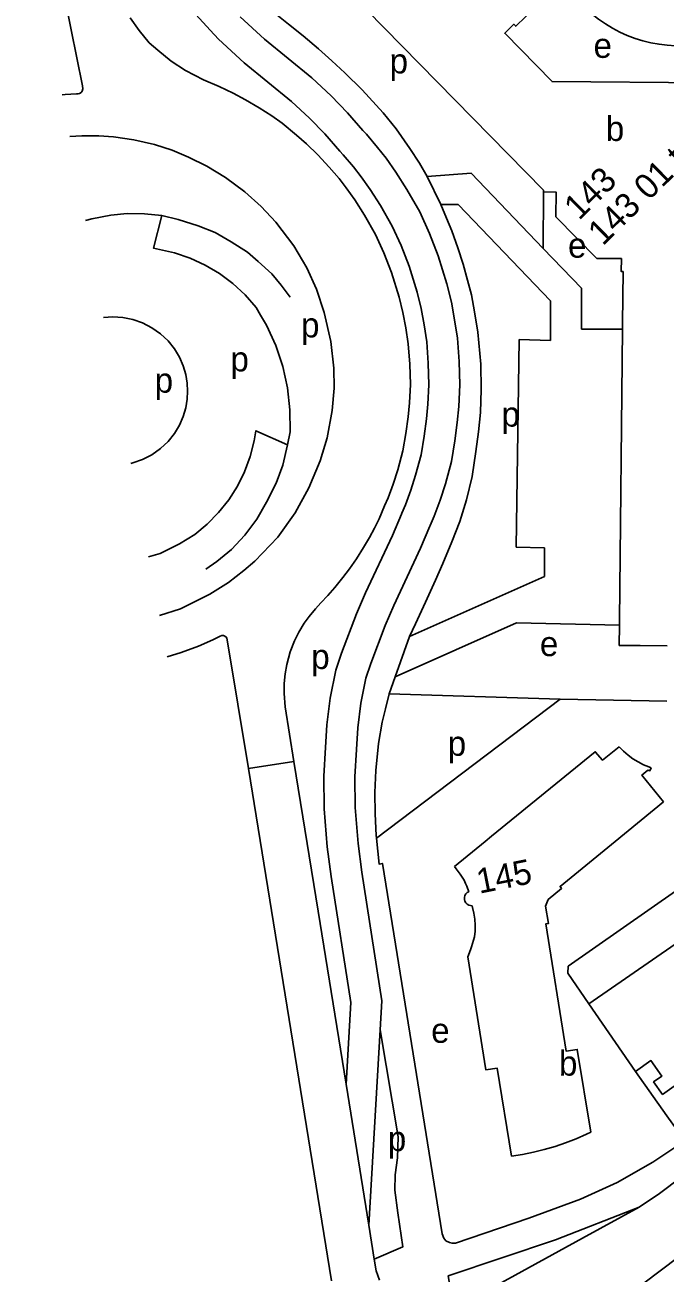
# Model space of a CAD drawing. Extents: x 159261 to 160849, y 382514 to 384534.
# Drawn here: x 159331.2 to 159434.5, y 383430.4 to 383631.8 of the extents above; entities that cross this region are included whole.
import ezdxf

# ---------------------------------------------------------------- set-up
doc = ezdxf.new("R2010")
doc.units = 0
for name, color, linetype in [('BLT_Basislijn', 7, 'Continuous'), ('BLT_Bebouwing', 7, 'Continuous'), ('BLT_Centroide', 7, 'Continuous'), ('BLT_Huisnummer_reeks', 7, 'Continuous'), ('BLT_Vlakafsluiter', 7, 'Continuous')]:
    doc.layers.add(name, color=color, linetype=linetype)

msp = doc.modelspace()

# ---------------------------------------------------------------- linework, layer by layer
at = {"layer": 'BLT_Basislijn'}
for p, q in [((159396.12, 383607.31), (159398.32, 383602.79)), ((159414.91, 383604.83), (159414.85, 383595.7)), ((159421.02, 383582.65), (159427.63, 383582.65)), ((159410.94, 383581.03), (159410.5, 383547.5)), ((159410.94, 383581.03), (159416.02, 383580.87)), ((159410.5, 383547.5), (159415.03, 383547.4)), ((159415.04, 383542.74), (159415.03, 383547.4)), ((159415.04, 383542.74), (159393.25, 383533.09)), ((159410.53, 383535.26), (159390.94, 383526.55)), ((159410.53, 383535.26), (159427.14, 383534.9)), ((159393.25, 383533.09), (159390.94, 383526.55)), ((159390.94, 383526.55), (159389.98, 383523.83)), ((159389.98, 383523.83), (159417.58, 383522.94)), ((159417.58, 383522.94), (159434.78, 383522.62)), ((159456.51, 383497.57), (159422.23, 383473.79)), ((159383.01, 383460.82), (159383.79, 383474.02)), ((159388.54, 383469.58), (159388.82, 383474.26)), ((159429.76, 383462.87), (159422.23, 383473.79)), ((159386.68, 383438.08), (159388.54, 383469.58))]:
    msp.add_line(p, q, dxfattribs=at)
for points in [[(159337.17, 383620.51), (159337.66, 383620.55), (159339.48, 383620.64), (159339.77, 383620.64), (159340, 383620.72), (159340.23, 383620.87), (159340.41, 383621.11), (159340.54, 383621.47), (159340.49, 383621.94), (159337.73, 383635.51), (159335.41, 383645.78), (159331.18, 383663.3)], [(159351.83, 383662.22), (159352.73, 383660.02), (159354.89, 383655.62), (159357.39, 383651.19), (159360, 383647.14), (159363.37, 383642.71), (159365.87, 383639.52), (159368.35, 383636.77), (159371.06, 383634.06), (159373.7, 383631.88), (159376.07, 383630), (159378.58, 383627.91), (159380.71, 383625.99), (159382.83, 383624.07), (159385.62, 383621.28), (159389, 383617.58), (159391.09, 383615), (159393.29, 383611.81), (159394.9, 383609.44), (159396.12, 383607.31)], [(159415.94, 383643.23), (159416.42, 383641.99), (159416.98, 383640.77), (159417.6, 383639.6), (159418.3, 383638.46), (159419.06, 383637.36), (159419.89, 383636.32), (159420.78, 383635.33), (159421.73, 383634.39), (159422.73, 383633.51), (159423.78, 383632.69), (159424.88, 383631.93), (159426.02, 383631.24), (159427.2, 383630.63), (159428.42, 383630.08), (159429.67, 383629.61), (159430.94, 383629.21), (159432.24, 383628.9), (159433.55, 383628.65), (159434.87, 383628.49), (159436.2, 383628.41), (159437.4, 383628.41)], [(159348.15, 383632.92), (159349.6, 383630.9), (159351.25, 383628.91), (159352.62, 383627.69), (159354.81, 383625.91), (159357.09, 383624.44), (159360.02, 383622.92), (159362.56, 383621.85), (159364.81, 383620.77), (159366.8, 383619.7), (159369, 383618.4), (159371.03, 383617.08), (159372.68, 383615.93), (159375.01, 383614), (159376.61, 383612.6), (159378.48, 383610.81), (159380.3, 383608.84), (159381.88, 383606.97), (159383.05, 383605.47), (159384.42, 383603.54), (159386, 383601.08), (159387.78, 383597.95), (159389.12, 383595), (159390.36, 383591.84), (159391.59, 383587.86), (159392.21, 383585.37), (159392.66, 383582.88), (159393.05, 383580.3), (159393.29, 383577.04), (159393.4, 383573.75), (159393.25, 383570.81), (159393.02, 383568.53), (159392.68, 383565.85), (159392.2, 383563.03), (159391.37, 383559.98), (159390.65, 383557.68), (159389.83, 383555.48), (159389.24, 383554.14), (159388.38, 383552.08), (159387.61, 383550.57), (159386.82, 383549.03), (159385.86, 383547.43), (159384.73, 383545.61), (159383.58, 383544), (159382.51, 383542.59), (159381.21, 383540.99), (159380.05, 383539.67), (159378.96, 383538.5), (159378.07, 383537.52), (159377.05, 383536.32), (159376.28, 383535.23), (159375.41, 383533.76), (159374.72, 383532.37), (159374.02, 383530.62), (159373.47, 383528.56), (159373.19, 383527.05), (159373.03, 383525.5), (159373, 383523.89), (159373.2, 383521.75), (159374.6, 383512.9)], [(159358.19, 383634.12), (159361.07, 383630.91), (159362.42, 383629.5), (159366.56, 383625.67), (159374.2, 383619.43), (159377.13, 383616.73), (159379.58, 383614.2), (159381.99, 383611.42), (159382.55, 383610.82), (159384.21, 383608.86), (159385.45, 383607.26), (159386.9, 383605.21), (159388.56, 383602.63), (159390.46, 383599.32), (159391.89, 383596.17), (159393.19, 383592.83), (159394.49, 383588.67), (159395.15, 383586), (159395.62, 383583.37), (159396.04, 383580.64), (159396.29, 383577.2), (159396.4, 383573.72), (159396.24, 383570.58), (159396, 383568.19), (159395.64, 383565.41), (159395.13, 383562.39), (159394.25, 383559.14), (159393.49, 383556.7), (159392.61, 383554.35), (159392, 383552.97), (159391.95, 383552.84), (159390.49, 383549.36), (159386.18, 383540.12), (159384.72, 383536.76), (159382.29, 383530.39), (159381.38, 383527.65), (159380.44, 383523.14), (159379.94, 383518.82), (159379.68, 383515.16), (159379.44, 383510.53), (159379.48, 383505.27), (159379.99, 383499.13), (159380.62, 383494.34), (159383.79, 383474.02)], [(159365.93, 383633.07), (159369.84, 383629.45), (159377.48, 383623.21), (159380.62, 383620.31), (159383.27, 383617.58), (159385.72, 383614.76), (159386.3, 383614.13), (159388.09, 383612.01), (159389.47, 383610.25), (159391.05, 383608.01), (159392.84, 383605.23), (159394.91, 383601.6), (159396.5, 383598.11), (159397.91, 383594.49), (159399.3, 383590.01), (159400.04, 383587.04), (159400.55, 383584.19), (159401.01, 383581.21), (159401.28, 383577.46), (159401.4, 383573.67), (159401.23, 383570.2), (159400.97, 383567.62), (159400.59, 383564.67), (159400.02, 383561.32), (159399.05, 383557.74), (159398.22, 383555.08), (159397.24, 383552.48), (159396.6, 383551.01), (159396.56, 383550.91), (159395.06, 383547.33), (159390.74, 383538.07), (159389.35, 383534.88), (159387, 383528.72), (159386.22, 383526.35), (159385.38, 383522.34), (159384.92, 383518.36), (159384.68, 383514.86), (159384.45, 383510.41), (159384.48, 383505.5), (159384.97, 383499.66), (159385.57, 383495.05), (159388.82, 383474.26)], [(159352.89, 383536.46), (159356.31, 383537.53), (159361.03, 383539.92), (159364.05, 383541.82), (159366.5, 383543.71), (159368.27, 383545.23), (159371.98, 383549.1), (159374.8, 383553.02), (159377.03, 383557.07), (159378.85, 383561.43), (159379.98, 383565.14), (159380.77, 383569.53), (159381.08, 383573.14), (159381.02, 383576.36), (159380.56, 383580.69), (159379.5, 383585.39), (159378.26, 383589.14), (159376.66, 383592.55), (159374.57, 383596.12), (159371.69, 383599.93), (159369.29, 383602.48), (159366.69, 383604.82), (159363.56, 383607.13), (159360.52, 383608.98), (159357.59, 383610.42), (159354.95, 383611.55), (159352.07, 383612.48), (159348.77, 383613.23), (159345.49, 383613.7), (159343.09, 383613.87), (159340.38, 383613.88), (159338.42, 383613.77)], [(159396.12, 383607.31), (159403.19, 383607.85), (159414.85, 383595.7)], [(159398.32, 383602.79), (159399.23, 383600.59), (159400.07, 383598.54), (159401.08, 383595.79), (159401.94, 383593.15), (159402.63, 383590.57), (159403.25, 383588.2), (159403.76, 383585.49), (159404.27, 383582.17), (159404.79, 383577.04), (159404.83, 383572.92), (159404.72, 383569.25), (159404.41, 383566.13), (159403.98, 383562.93), (159403.35, 383558.92), (159402.46, 383555.14), (159401.39, 383551.64), (159400.12, 383548.34), (159398.63, 383544.87), (159397.45, 383542.19), (159395.84, 383538.62), (159394.25, 383535.13), (159393.25, 383533.09)], [(159398.32, 383602.79), (159401.11, 383602.79), (159416.02, 383587.26), (159416.02, 383580.87)], [(159340.95, 383600.21), (159341.96, 383600.48), (159345.05, 383601.06), (159347.69, 383601.34), (159350.48, 383601.3), (159353.26, 383601.03)], [(159353.26, 383601.03), (159351.94, 383595.74), (159355.31, 383595.02), (159357.85, 383594.16), (159360.29, 383593.03), (159362.6, 383591.65), (159364.76, 383590.03), (159366.73, 383588.2), (159368.5, 383586.18), (159369.21, 383584.96), (159370.18, 383583.3), (159371.66, 383580.05), (159372.79, 383576.67), (159373.56, 383573.19), (159373.96, 383569.66), (159374, 383566.1), (159373.57, 383564.02)], [(159353.26, 383601.03), (159355.93, 383600.37), (159359.16, 383599.34), (159361.87, 383598.25), (159364.48, 383596.77), (159367.13, 383595.12), (159368.84, 383593.61), (159371.01, 383591.62), (159372.55, 383589.76), (159374, 383587.83)], [(159414.85, 383595.7), (159421.02, 383589.27), (159421.02, 383582.65)], [(159357.44, 383572.67), (159357.37, 383573.98), (159357.14, 383575.34), (159356.73, 383576.75), (159356.12, 383578.15), (159355.3, 383579.51), (159354.28, 383580.79), (159353.06, 383581.94), (159351.68, 383582.91), (159350.18, 383583.69), (159348.59, 383584.25), (159346.98, 383584.57), (159345.37, 383584.67), (159343.86, 383584.56)], [(159348.27, 383561.02), (159348.59, 383561.09), (159350.18, 383561.64), (159351.68, 383562.42), (159353.06, 383563.4), (159354.28, 383564.55), (159355.3, 383565.82), (159356.12, 383567.19), (159356.73, 383568.59), (159357.14, 383569.99), (159357.37, 383571.36), (159357.44, 383572.67)], [(159373.57, 383564.02), (159368.46, 383566.27), (159368.19, 383564.67), (159367.54, 383562.14), (159366.63, 383559.68), (159365.47, 383557.34), (159364.07, 383555.13), (159362.44, 383553.08), (159360.61, 383551.21), (159358.6, 383549.54), (159356.12, 383548.01), (159353, 383546.5), (159351.11, 383545.93)], [(159373.57, 383564.02), (159372.79, 383560.73), (159371.73, 383557.82), (159370.18, 383554.74), (159368.59, 383552), (159366.7, 383549.44), (159364.5, 383547.12), (159362.18, 383545.16), (159360.4, 383543.93)], [(159367.26, 383511.76), (159363.84, 383532.55), (159363.79, 383532.79), (159363.67, 383532.99), (159363.46, 383533.16), (159363.22, 383533.25), (159362.94, 383533.25), (159362.67, 383533.14), (159361.49, 383532.55), (159359.21, 383531.54), (159356.38, 383530.49), (159354.15, 383529.8)], [(159389.98, 383523.83), (159389.38, 383521.41), (159388.84, 383519.26), (159388.28, 383515.83), (159387.8, 383511.48), (159387.66, 383507.89), (159387.73, 383504.46), (159387.9, 383500.99), (159387.94, 383500.54)], [(159417.58, 383522.94), (159387.94, 383500.54)], [(159374.6, 383512.9), (159378.51, 383488.75), (159383.01, 383460.82)], [(159380.67, 383429.12), (159367.26, 383511.76)], [(159422.23, 383473.79), (159418.8, 383478.76), (159418.9, 383479.86), (159458, 383507.23)], [(159387.94, 383500.54), (159388.35, 383496.34), (159388.9, 383496.45), (159398.52, 383436.7), (159398.78, 383435.98), (159399.15, 383435.57), (159399.71, 383435.26), (159400.13, 383435.17), (159400.66, 383435.2)], [(159430.35, 383440.97), (159433.6, 383443.17), (159492.79, 383487.8), (159505.65, 383497.5)], [(159388.54, 383469.58), (159391.44, 383452.32), (159391.34, 383448.96), (159390.94, 383446.23), (159390.9, 383443.72), (159391.4, 383440.07), (159392.21, 383434.6), (159387.56, 383432.62)], [(159437.72, 383451.68), (159432.56, 383448.25), (159426.76, 383444.96), (159420.88, 383442.27), (159412.54, 383439.19), (159400.66, 383435.2)], [(159400.42, 383424.47), (159399.52, 383429.88), (159416.81, 383435.73), (159430.35, 383440.97)], [(159430.35, 383440.97), (159421.19, 383435.97), (159402.7, 383425.8), (159400.42, 383424.47)], [(159386.68, 383438.08), (159387.56, 383432.62)], [(159439.63, 383435.19), (159399.52, 383404.89)], [(159387.56, 383432.62), (159387.87, 383430.7), (159388.43, 383429.2)]]:
    msp.add_lwpolyline(points, dxfattribs=at)
at = {"layer": 'BLT_Bebouwing'}
for p, q in [((159427.15, 383535.65), (159427.63, 383582.65)), ((159427.63, 383582.65), (159427.64, 383583.62)), ((159427.14, 383534.9), (159427.15, 383535.65)), ((159402.07, 383493.77), (159402.31, 383493.2)), ((159403.75, 383484.6), (159403.25, 383483))]:
    msp.add_line(p, q, dxfattribs=at)
for points in [[(159414.91, 383604.83), (159414.91, 383605.09), (159377.74, 383643)], [(159441.32, 383622.41), (159416.28, 383622.63), (159408.65, 383630.42), (159410.11, 383631.88), (159410.41, 383631.56), (159413.55, 383634.59), (159407.48, 383640.88)], [(159427.64, 383583.62), (159427.73, 383591.98), (159427.44, 383591.98), (159427.47, 383594.06), (159423.52, 383594.06), (159416.9, 383600.8), (159416.93, 383604.81), (159414.91, 383604.83)], [(159430.52, 383531.61), (159427.11, 383531.63), (159427.14, 383534.9)], [(159434.85, 383531.6), (159430.52, 383531.61)], [(159427.13, 383515.26), (159424.43, 383513.1), (159423.26, 383514.48), (159406.52, 383500.86)], [(159427.13, 383515.26), (159427.81, 383514.56), (159428.54, 383513.92), (159429.33, 383513.34), (159430.15, 383512.83), (159431.02, 383512.39), (159431.92, 383512.03), (159432.27, 383511.9)], [(159434.29, 383506.4), (159430.77, 383510.72), (159431.73, 383511.52), (159432.07, 383511.42), (159432.27, 383511.9)], [(159422.53, 383453.1), (159420.34, 383466.43), (159418.57, 383466.16), (159415.26, 383486.7), (159415.68, 383486.76), (159415.22, 383489.58), (159415.62, 383490.61), (159417.82, 383492.42), (159417.56, 383492.74), (159426.45, 383500), (159434.29, 383506.4)], [(159406.52, 383500.86), (159405.47, 383500), (159400.5, 383495.96)], [(159402.07, 383493.77), (159401.46, 383494.71), (159400.79, 383495.61), (159400.5, 383495.96)], [(159402.84, 383491.89), (159402.57, 383491.74), (159402.36, 383491.53), (159402.2, 383491.26), (159402.12, 383490.97), (159402.12, 383490.66), (159402.2, 383490.37), (159402.35, 383490.1), (159402.57, 383489.88), (159402.83, 383489.73), (159403.12, 383489.65), (159403.36, 383489.64)], [(159402.84, 383491.89), (159402.49, 383492.8), (159402.31, 383493.2)], [(159403.75, 383484.6), (159403.85, 383485.55), (159403.87, 383486.51), (159403.81, 383487.46), (159403.67, 383488.41), (159403.45, 383489.34), (159403.36, 383489.64)], [(159402.68, 383481.4), (159403.09, 383482.49), (159403.25, 383483)], [(159402.68, 383481.4), (159405.59, 383463.13), (159407.41, 383463.43), (159409.7, 383449.21)], [(159429.76, 383462.87), (159432.24, 383464.63), (159434.01, 383462.15), (159432.67, 383461.2), (159434.11, 383459.17), (159438.27, 383462.12)], [(159437.72, 383451.68), (159434.82, 383455.75), (159429.76, 383462.87)], [(159409.7, 383449.21), (159411.49, 383449.48), (159413.26, 383449.84), (159415.02, 383450.27), (159416.76, 383450.78), (159418.47, 383451.36), (159420.16, 383452.02), (159421.81, 383452.76), (159422.53, 383453.1)]]:
    msp.add_lwpolyline(points, dxfattribs=at)
at = {"layer": 'BLT_Vlakafsluiter'}
for p, q in [((159374.6, 383512.9), (159367.26, 383511.76)), ((159383.01, 383460.82), (159386.68, 383438.08))]:
    msp.add_line(p, q, dxfattribs=at)

# ---------------------------------------------------------------- texts
at = {"layer": 'BLT_Centroide'}
for s, p in [('e', (159422.97, 383626.46)), ('p', (159390.05, 383623.95)), ('b', (159424.95, 383613.05)), ('e', (159418.85, 383594.21)), ('p', (159375.75, 383581.35)), ('p', (159364.35, 383575.86)), ('p', (159352.12, 383572.43)), ('p', (159408.11, 383566.95)), ('e', (159414.31, 383529.91)), ('p', (159377.4, 383527.84)), ('p', (159399.43, 383513.83)), ('e', (159396.76, 383467.51)), ('b', (159417.39, 383462.22)), ('p', (159389.76, 383450.04))]:
    msp.add_text(s, height=4, dxfattribs=at).set_placement(p)
at = {"layer": 'BLT_Huisnummer_reeks'}
for s, rotation, p in [('143 01 t/m 143 337', 44.538, (159424.47, 383596.02)), ('143', 44.538, (159420.62, 383600.11)), ('145', 11.2727, (159404.52, 383491.56))]:
    msp.add_text(s, height=4, rotation=rotation, dxfattribs=at).set_placement(p)

doc.saveas('drawing.dxf')
